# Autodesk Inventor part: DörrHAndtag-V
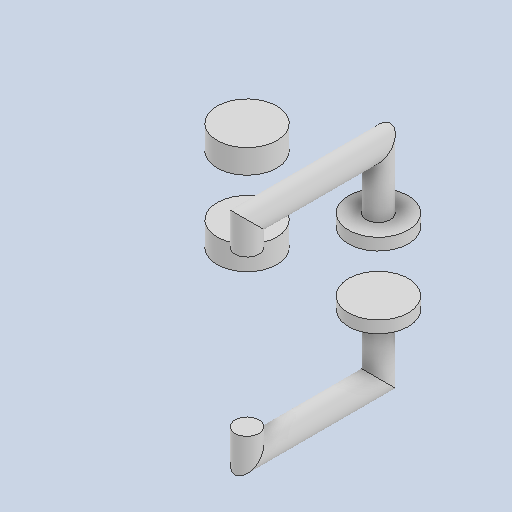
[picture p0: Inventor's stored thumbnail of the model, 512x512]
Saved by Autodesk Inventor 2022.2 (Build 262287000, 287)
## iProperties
Created: 2019-06
Part Number: DörrHAndtag-V
Material: Generic
Document SubType Name: Modeling
Designer: cl
Density: 1 g/cm^3
Appearance: Default
Author: cl
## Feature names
1. Extrusion1
2. Extrusion2
3. Sweep1
4. Mirror1
## Parameters: d3 = 0, d5 = 0, d8 = 0, d10 = 0, d15 = 0, d16 = 0, d17 = 25 mm
